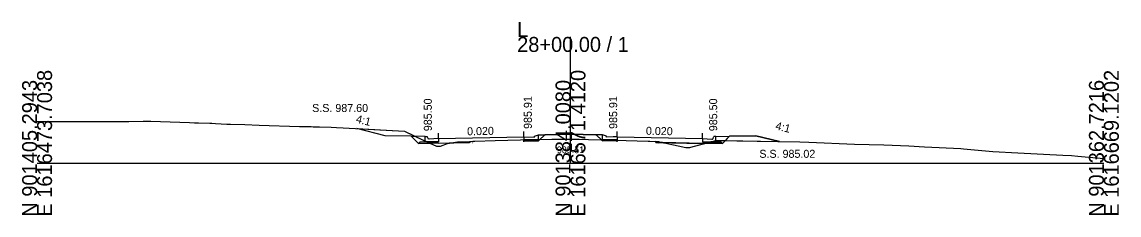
# Model space of a CAD drawing. Extents: x 1009 to 7438, y -1586 to 7964.
# Drawn here: x 2032.1 to 2237.7, y 5914 to 5950.2 of the extents above; entities that cross this region are included whole.
import ezdxf

# ---------------------------------------------------------------- set-up
doc = ezdxf.new("R2010")
doc.units = 0
for name, color, linetype in [('Exist Cross Section Cell', 7, 'Continuous'), ('Exist XS Center Line Elevation Label', 7, 'Continuous'), ('Exist XS Ground Line', 7, 'Continuous'), ('Prop XS Dump Level', 7, 'Continuous'), ('Prop XS Earthwork Shape', 7, 'Continuous'), ('Prop XS EOT Tick Mark', 7, 'Continuous'), ('Prop XS Finish Grade', 7, 'Continuous'), ('Prop XS Finish Grade CurbGutter', 7, 'Continuous'), ('Prop XS Finish Grade Earthwork', 7, 'Continuous'), ('Prop XS Finish Grade Pavement', 7, 'Continuous'), ('Prop XS Hydro Elevations', 7, 'Continuous'), ('Prop XS Pvmt Edge Slope', 7, 'Continuous'), ('Prop XS SE Text', 7, 'Continuous'), ('Prop XS Side Slope Text', 7, 'Continuous'), ('Prop XS SS Elevation Text', 7, 'Continuous'), ('Prop XS Subgrade CurbGutter', 7, 'Continuous'), ('Prop XS Subgrade Earthwork', 7, 'Continuous')]:
    doc.layers.add(name, color=color, linetype=linetype)

msp = doc.modelspace()

# ---------------------------------------------------------------- linework, layer by layer
at = {"layer": 'Exist Cross Section Cell'}
for p, q in [((2134.89, 5923.73), (2134.89, 5947.38)), ((2034.89, 5923.73), (2134.89, 5923.73)), ((2134.89, 5923.73), (2234.89, 5923.73))]:
    msp.add_line(p, q, dxfattribs=at)
at = {"layer": 'Exist XS Ground Line'}
for p, q in [((2034.89, 5931.57), (2037.52, 5931.56)), ((2037.52, 5931.56), (2052.1, 5931.52)), ((2052.1, 5931.52), (2054.79, 5931.61)), ((2054.79, 5931.61), (2055.53, 5931.61)), ((2055.53, 5931.61), (2056.23, 5931.6)), ((2056.23, 5931.6), (2063.46, 5931.37)), ((2063.46, 5931.37), (2064.38, 5931.33)), ((2064.38, 5931.33), (2065.12, 5931.3)), ((2065.12, 5931.3), (2067.26, 5931.25)), ((2067.26, 5931.25), (2067.66, 5931.22)), ((2067.66, 5931.22), (2068.32, 5931.2)), ((2068.32, 5931.2), (2070.49, 5931.04)), ((2070.49, 5931.04), (2071.17, 5931.03)), ((2071.17, 5931.03), (2073.85, 5930.99)), ((2073.85, 5930.99), (2076.54, 5930.88)), ((2076.54, 5930.88), (2084.08, 5930.63)), ((2084.08, 5930.63), (2086.27, 5930.61)), ((2086.27, 5930.61), (2086.63, 5930.58)), ((2086.63, 5930.58), (2087.31, 5930.58)), ((2087.31, 5930.58), (2087.86, 5930.55)), ((2087.86, 5930.55), (2090.03, 5930.46)), ((2090.03, 5930.46), (2091.02, 5930.4)), ((2091.02, 5930.4), (2092.28, 5930.35)), ((2092.28, 5930.35), (2103.78, 5929.76)), ((2103.78, 5929.76), (2107.13, 5928.14)), ((2107.13, 5928.14), (2109.8, 5926.92)), ((2111.85, 5927.43), (2113.73, 5927.75)), ((2113.73, 5927.75), (2115.97, 5927.81)), ((2115.97, 5927.81), (2116.56, 5927.86)), ((2116.56, 5927.86), (2116.94, 5927.89)), ((2116.94, 5927.89), (2120.75, 5927.99)), ((2120.75, 5927.99), (2127.89, 5928.15)), ((2127.89, 5928.15), (2131.4, 5928.22)), ((2131.4, 5928.22), (2133.32, 5928.26)), ((2133.32, 5928.26), (2134.89, 5928.24)), ((2134.89, 5928.24), (2136.5, 5928.22)), ((2136.5, 5928.22), (2138.24, 5928.18)), ((2138.24, 5928.18), (2145.33, 5927.99)), ((2145.33, 5927.99), (2149.47, 5927.88)), ((2149.47, 5927.88), (2149.78, 5927.86)), ((2149.78, 5927.86), (2150.89, 5927.8)), ((2150.89, 5927.8), (2151.48, 5927.74)), ((2151.48, 5927.74), (2151.81, 5927.63)), ((2157.89, 5926.86), (2162.22, 5928.01)), ((2162.22, 5928.01), (2173.76, 5927.78)), ((2173.76, 5927.78), (2177.88, 5927.74)), ((2109.8, 5926.92), (2110.55, 5926.92)), ((2110.55, 5926.92), (2111.85, 5927.43)), ((2151.81, 5927.63), (2152.75, 5927.51)), ((2152.75, 5927.51), (2156.5, 5926.68)), ((2156.5, 5926.68), (2157.25, 5926.68)), ((2157.25, 5926.68), (2157.89, 5926.86)), ((2177.88, 5927.74), (2179.55, 5927.67)), ((2179.55, 5927.67), (2188.11, 5927.31)), ((2188.11, 5927.31), (2193.61, 5927.16)), ((2193.61, 5927.16), (2198.34, 5927)), ((2198.34, 5927), (2201.24, 5926.83)), ((2201.24, 5926.83), (2208.09, 5926.47)), ((2208.09, 5926.47), (2208.55, 5926.44)), ((2208.55, 5926.44), (2214.05, 5925.95)), ((2214.05, 5925.95), (2218.76, 5925.71)), ((2218.76, 5925.71), (2227.18, 5925.27)), ((2227.18, 5925.27), (2228.84, 5925.17)), ((2228.84, 5925.17), (2230.01, 5925.05)), ((2230.01, 5925.05), (2234.89, 5924.63))]:
    msp.add_line(p, q, dxfattribs=at)
at = {"layer": 'Prop XS Dump Level'}
for p, q in [((2110.14, 5928.35), (2126.14, 5928.67)), ((2110.14, 5928.35), (2126.14, 5928.67)), ((2143.64, 5928.67), (2159.64, 5928.35)), ((2143.64, 5928.67), (2159.64, 5928.35))]:
    msp.add_line(p, q, dxfattribs=at)
at = {"layer": 'Prop XS Earthwork Shape'}
for points in [[(2094.85, 5930.22), (2103.78, 5929.76), (2105.81, 5928.77), (2105.05, 5928.79), (2100.14, 5928.89)], [(2105.81, 5928.77), (2107.13, 5928.14), (2107.64, 5927.9), (2107.64, 5927.72), (2106.64, 5927.7), (2106.39, 5927.45), (2105.05, 5928.79)], [(2108.01, 5927.73), (2107.64, 5927.72), (2107.64, 5927.9)], [(2112.15, 5927.48), (2113.73, 5927.75), (2115.97, 5927.81), (2115.97, 5927.55)], [(2126.14, 5928.11), (2127.89, 5928.15), (2128.89, 5928.17), (2128.89, 5928.15), (2128.64, 5928.14), (2127.64, 5928.12), (2126.14, 5928.09)], [(2126.14, 5927.84), (2126.14, 5928.09), (2127.64, 5928.12), (2128.64, 5928.14), (2128.89, 5927.9)], [(2128.89, 5928.17), (2129.16, 5928.17), (2128.89, 5927.9), (2128.64, 5928.14), (2128.89, 5928.15)], [(2139.72, 5929.08), (2139.67, 5929.08), (2134.89, 5929.18), (2130.12, 5929.08), (2130.07, 5929.08), (2129.16, 5928.17), (2131.4, 5928.22), (2133.32, 5928.26), (2134.89, 5928.24), (2136.5, 5928.22), (2138.24, 5928.18), (2140.68, 5928.12)], [(2140.68, 5928.12), (2141.11, 5928.11), (2140.9, 5927.9)], [(2141.11, 5928.11), (2143.64, 5928.04), (2143.64, 5927.84), (2140.9, 5927.9)], [(2150.89, 5927.61), (2152.14, 5927.59), (2151.81, 5927.63), (2151.48, 5927.74), (2150.89, 5927.8)], [(2161.22, 5927.74), (2162.14, 5927.72), (2163.14, 5927.7), (2163.39, 5927.45), (2160.35, 5927.51)], [(2161.22, 5927.74), (2162.14, 5927.99), (2162.14, 5927.72)], [(2162.14, 5927.99), (2162.22, 5928.01), (2163.92, 5927.98), (2163.39, 5927.45), (2163.14, 5927.7), (2162.14, 5927.72)], [(2163.92, 5927.98), (2173.76, 5927.78), (2174.09, 5927.78), (2169.64, 5928.89), (2164.73, 5928.79)], [(2108.01, 5927.73), (2107.64, 5927.72), (2106.64, 5927.7), (2106.39, 5927.45), (2108.54, 5927.49)], [(2108.54, 5927.49), (2109.8, 5926.92), (2110.55, 5926.92), (2111.85, 5927.43), (2112.15, 5927.48), (2110.14, 5927.44), (2110.14, 5927.52)], [(2152.14, 5927.59), (2152.75, 5927.51), (2156.5, 5926.68), (2157.25, 5926.68), (2157.89, 5926.86), (2160.35, 5927.51), (2159.64, 5927.52), (2159.64, 5927.44)]]:
    msp.add_lwpolyline(points, close=True, dxfattribs=at)
at = {"layer": 'Prop XS EOT Tick Mark'}
for p, q in [((2110.14, 5928.35), (2110.14, 5929.35)), ((2126.14, 5928.67), (2126.14, 5929.67)), ((2143.64, 5928.67), (2143.64, 5929.67)), ((2159.64, 5928.35), (2159.64, 5929.35))]:
    msp.add_line(p, q, dxfattribs=at)
at = {"layer": 'Prop XS Finish Grade'}
for p, q in [((2107.64, 5928.73), (2105.05, 5928.79)), ((2128.89, 5929.05), (2130.12, 5929.08)), ((2140.89, 5929.05), (2139.67, 5929.08)), ((2162.14, 5928.73), (2164.73, 5928.79))]:
    msp.add_line(p, q, dxfattribs=at)
at = {"layer": 'Prop XS Finish Grade CurbGutter'}
for p, q in [((2107.64, 5928.73), (2107.89, 5928.73)), ((2107.89, 5928.73), (2108.02, 5928.71)), ((2108.11, 5928.61), (2108.02, 5928.71)), ((2108.18, 5928.36), (2108.11, 5928.61)), ((2108.27, 5928.27), (2108.18, 5928.36)), ((2108.39, 5928.25), (2108.27, 5928.27)), ((2110.14, 5928.35), (2108.39, 5928.25)), ((2126.14, 5928.67), (2128.14, 5928.63)), ((2128.14, 5928.8), (2128.89, 5929.05)), ((2128.14, 5928.63), (2128.14, 5928.8)), ((2141.64, 5928.8), (2140.89, 5929.05)), ((2141.64, 5928.63), (2141.64, 5928.8)), ((2143.64, 5928.67), (2141.64, 5928.63)), ((2143.64, 5928.67), (2142.89, 5928.66)), ((2159.64, 5928.35), (2161.39, 5928.25)), ((2161.39, 5928.25), (2161.52, 5928.27)), ((2161.52, 5928.27), (2161.61, 5928.36)), ((2161.61, 5928.36), (2161.68, 5928.61)), ((2161.68, 5928.61), (2161.77, 5928.71)), ((2161.89, 5928.73), (2161.77, 5928.71)), ((2162.14, 5928.73), (2161.89, 5928.73))]:
    msp.add_line(p, q, dxfattribs=at)
at = {"layer": 'Prop XS Finish Grade Earthwork'}
for p, q in [((2100.14, 5928.89), (2094.85, 5930.22)), ((2105.05, 5928.79), (2100.14, 5928.89)), ((2130.12, 5929.08), (2134.89, 5929.18)), ((2134.89, 5929.18), (2139.67, 5929.08)), ((2164.73, 5928.79), (2169.64, 5928.89)), ((2169.64, 5928.89), (2174.09, 5927.78))]:
    msp.add_line(p, q, dxfattribs=at)
at = {"layer": 'Prop XS Finish Grade Pavement'}
for p, q in [((2110.14, 5928.35), (2126.14, 5928.67)), ((2143.64, 5928.67), (2159.64, 5928.35))]:
    msp.add_line(p, q, dxfattribs=at)
at = {"layer": 'Prop XS Pvmt Edge Slope'}
for p, q in [((2127.64, 5928.12), (2128.89, 5928.15)), ((2127.64, 5928.12), (2128.64, 5928.14)), ((2128.64, 5928.14), (2128.89, 5927.9)), ((2142.14, 5928.12), (2140.89, 5928.15)), ((2141.14, 5928.14), (2140.9, 5927.9)), ((2142.14, 5928.12), (2141.14, 5928.14)), ((2106.64, 5927.7), (2106.39, 5927.45)), ((2107.64, 5927.72), (2106.64, 5927.7)), ((2162.14, 5927.72), (2163.14, 5927.7)), ((2163.14, 5927.7), (2163.39, 5927.45))]:
    msp.add_line(p, q, dxfattribs=at)
at = {"layer": 'Prop XS Subgrade CurbGutter'}
for p, q in [((2107.64, 5927.72), (2107.64, 5928.73)), ((2110.14, 5927.77), (2107.64, 5927.72)), ((2110.14, 5928.35), (2110.14, 5927.77)), ((2126.14, 5928.67), (2126.14, 5928.09)), ((2126.14, 5928.09), (2127.64, 5928.12)), ((2128.89, 5928.15), (2128.89, 5929.05)), ((2140.89, 5928.15), (2140.89, 5929.05)), ((2143.64, 5928.09), (2142.14, 5928.12)), ((2143.64, 5928.67), (2143.64, 5928.09)), ((2159.64, 5928.35), (2159.64, 5927.77)), ((2159.64, 5927.77), (2162.14, 5927.72)), ((2162.14, 5927.72), (2162.14, 5928.73))]:
    msp.add_line(p, q, dxfattribs=at)
at = {"layer": 'Prop XS Subgrade Earthwork'}
for p, q in [((2106.39, 5927.45), (2105.05, 5928.79)), ((2115.97, 5927.55), (2115.97, 5927.81)), ((2126.14, 5927.76), (2126.14, 5928.11)), ((2126.14, 5927.84), (2128.89, 5927.9)), ((2126.14, 5927.76), (2126.14, 5927.84)), ((2128.89, 5927.9), (2130.07, 5929.08)), ((2140.9, 5927.9), (2139.72, 5929.08)), ((2143.64, 5927.84), (2140.9, 5927.9)), ((2143.64, 5927.76), (2143.64, 5928.04)), ((2143.64, 5927.76), (2143.64, 5927.84)), ((2150.89, 5927.61), (2150.89, 5927.8)), ((2163.39, 5927.45), (2164.73, 5928.79)), ((2110.14, 5927.52), (2106.39, 5927.45)), ((2115.97, 5927.55), (2110.14, 5927.44)), ((2110.14, 5927.44), (2110.14, 5927.52)), ((2150.89, 5927.61), (2159.64, 5927.44)), ((2159.64, 5927.44), (2159.64, 5927.52)), ((2159.64, 5927.52), (2163.39, 5927.45))]:
    msp.add_line(p, q, dxfattribs=at)

# ---------------------------------------------------------------- texts
at = {"layer": 'Exist Cross Section Cell'}
for s, p in [('L', (2124.89, 5947.38)), ('28+00.00 / 1', (2124.89, 5944.58))]:
    msp.add_text(s, height=2.8, dxfattribs=at).set_placement(p)
for s, p in [('E 1616473.7038', (2037.69, 5913.73)), ('E 1616571.4120', (2137.69, 5913.73)), ('E 1616669.1202', (2237.69, 5913.73)), ('N 901405.2943', (2034.89, 5913.73)), ('N 901384.0080', (2134.89, 5913.73)), ('N 901362.7216', (2234.89, 5913.73))]:
    msp.add_text(s, height=2.8, rotation=90, dxfattribs=at).set_placement(p)
at = {"layer": 'Exist XS Center Line Elevation Label'}
msp.add_text('985.51', height=1.25, dxfattribs=at).set_placement((2132.34, 5925.62))
at = {"layer": 'Prop XS Dump Level'}
for p in [(2115.97, 5927.51), (2115.97, 5927.51), (2150.89, 5927.5), (2150.89, 5927.5)]:
    msp.add_text('Eop', height=0.3, dxfattribs=at).set_placement(p)
at = {"layer": 'Prop XS Hydro Elevations'}
for s, p in [('985.91', (2127.64, 5930.16)), ('985.91', (2143.64, 5930.16)), ('985.50', (2108.89, 5929.73)), ('985.50', (2162.39, 5929.73))]:
    msp.add_text(s, height=1.5, rotation=90, dxfattribs=at).set_placement(p)
at = {"layer": 'Prop XS SE Text'}
for rotation, p in [(1.1458, (2115.52, 5928.96)), (358.8542, (2149.02, 5929.07))]:
    msp.add_text('0.020', height=1.5, rotation=rotation, dxfattribs=at).set_placement(p)
at = {"layer": 'Prop XS Side Slope Text'}
for p in [(2094.56, 5931.38), (2173.21, 5930.09)]:
    msp.add_text('4:1', height=1.5, rotation=345.9638, dxfattribs=at).set_placement(p)
at = {"layer": 'Prop XS SS Elevation Text'}
for s, p in [('S.S. 987.60', (2086.46, 5933.33)), ('S.S. 985.02', (2170.3, 5924.75))]:
    msp.add_text(s, height=1.5, dxfattribs=at).set_placement(p)

doc.saveas('drawing.dxf')
